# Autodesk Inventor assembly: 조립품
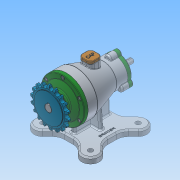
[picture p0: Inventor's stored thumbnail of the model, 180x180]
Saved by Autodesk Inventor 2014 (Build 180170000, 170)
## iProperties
Created: 2018-03
Part Number: 조립품
Document SubType Name: Assembly
Designer: net
Author: net
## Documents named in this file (15)
- C:\Users\net\Desktop\480307V1028\조립품.iam
- C:\Users\net\Desktop\480307V1028\본체.ipt
- C:\Users\net\Desktop\480307V1028\뒤커버.ipt
- C:\Users\net\Desktop\480307V1028\볼트 M4 x 12.ipt
- 볼트 M4 x 12.ipt
- C:\Users\net\Desktop\480307V1028\마개.ipt
- C:\Users\net\Desktop\480307V1028\베어링-6200.ipt
- C:\Users\net\Desktop\480307V1028\오일 실 10 20 7.ipt
- C:\Users\net\Desktop\480307V1028\축.ipt
- C:\Users\net\Desktop\480307V1028\키 5 x 5.ipt
- 키 5 x 5.ipt
- C:\Users\net\Desktop\480307V1028\베어링-6203.ipt
- C:\Users\net\Desktop\480307V1028\앞커버.ipt
- C:\Users\net\Desktop\480307V1028\오일 실 17 30 8.ipt
- C:\Users\net\Desktop\480307V1028\스프로킷.ipt
